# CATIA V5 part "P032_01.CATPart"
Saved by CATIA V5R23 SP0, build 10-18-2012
Part number: P032_01
Bounding box of the stored display mesh (mm): x 0.5 to 20.5, y -19.979 to 19.979, z -19.995 to 19.995
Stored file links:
  C:\wamp\www\COURS\CONCEPTION GMP1\TITRE 02-SEMESTRE 2\03-TP7-PRESSE MECANIQUE\eleve\P032_01.CATPart
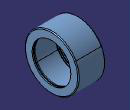
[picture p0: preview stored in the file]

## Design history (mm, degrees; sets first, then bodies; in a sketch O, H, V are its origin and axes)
Set1
  Plane1: type Offset, RefPlane yz-plane, Offset 10.5
  Point1: type OnCurve, Support Sketch1, RefPoint {extremum Reference Sketch1, Direction (1, 2, 3)}, Length 0
  Point2: type OnPlane, Support face of Solid1, RefPoint Point1, H 0, V 0, Direction (0, 1, 0)
Body1 (main body)
  Solid1: solid without history
  Sketch1 on Plane1, origin (10.5, 0, 0), H (0, 1, 0), V (0, 0, 1)
    projected circle E1 centre (0, 0) radius 20 from edge [face of Solid1 | face of Solid1]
